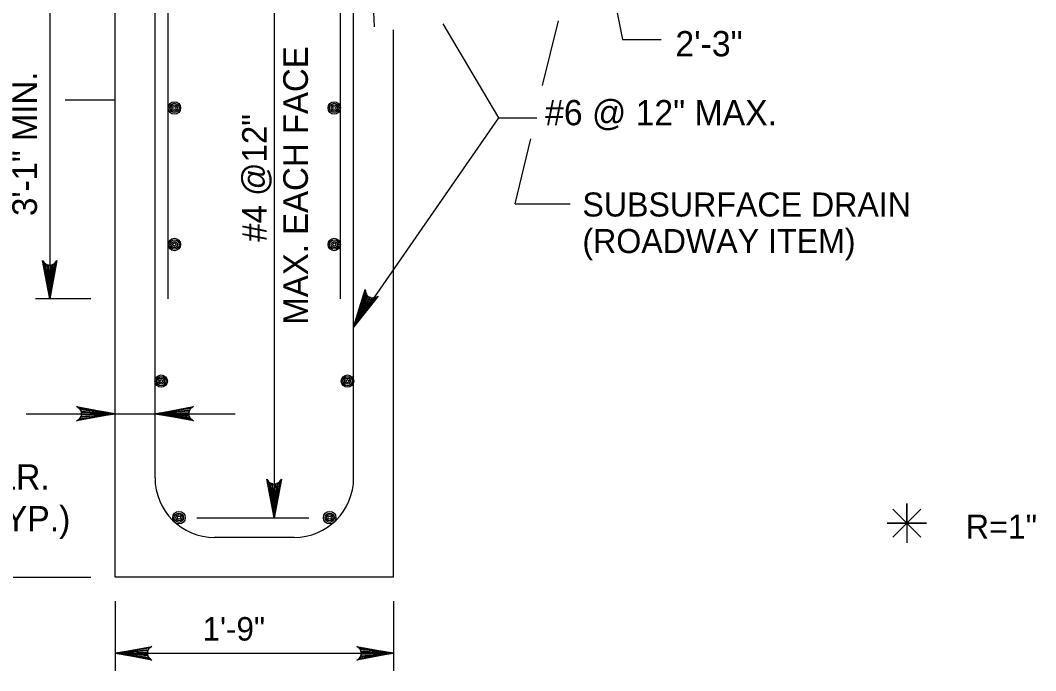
# Model space of a CAD drawing. Extents: x 638167 to 640248, y 296544 to 298920.
# Drawn here: x 639551.3 to 639681.1, y 298638.7 to 298721.8 of the extents above; entities that cross this region are included whole.
import ezdxf

# ---------------------------------------------------------------- set-up
doc = ezdxf.new("R2010")
doc.units = 0
doc.layers.add('1', color=7, linetype='Continuous')
doc.layers.add('50', color=7, linetype='Continuous')

# ---------------------------------------------------------------- blocks, each defined once
blk = doc.blocks.new('BAR')
at = {"layer": '50'}
for radius in [2, 1.5, 1, 0.5]:
    blk.add_circle((0, 0), radius, dxfattribs=at)

msp = doc.modelspace()

# ---------------------------------------------------------------- linework, layer by layer
at = {"layer": '1'}
for p, q in [((639583.8, 298762.96), (639583.8, 298658.27)), ((639563.48, 298650.66), (639563.48, 298751.04)), ((639595.38, 298750.89), (639596.57, 298721)), ((639555.1, 298737.02), (639555.1, 298686.22)), ((639568.56, 298663.36), (639568.56, 298737.02)), ((639570.25, 298686.22), (639570.25, 298737.02)), ((639592.26, 298686.22), (639592.26, 298737.02)), ((639593.95, 298663.36), (639593.95, 298737.02)), ((639627.44, 298723.85), (639628.33, 298719.38)), ((639618.11, 298713.47), (639620.12, 298721.75)), ((639599.03, 298650.66), (639599.03, 298720.59)), ((639605.33, 298721.38), (639612.48, 298709.34)), ((639628.33, 298719.38), (639633.26, 298719.38)), ((639563.48, 298711.62), (639557.09, 298711.62)), ((639612.48, 298709.34), (639593.95, 298682.63)), ((639612.48, 298709.34), (639617.35, 298709.34)), ((639614.59, 298698.39), (639616.59, 298706.68)), ((639614.59, 298698.39), (639621.63, 298698.39)), ((639560.34, 298686.22), (639553.3, 298686.22)), ((639552.1, 298671.55), (639578.82, 298671.55)), ((639573.91, 298658.27), (639588.23, 298658.27)), ((639664.66, 298657.57), (639664.66, 298657.57)), ((639586.33, 298655.74), (639576.18, 298655.74)), ((639502.18, 298650.66), (639560.34, 298650.66)), ((639599.03, 298650.66), (639563.48, 298650.66)), ((639563.48, 298647.62), (639563.48, 298638.72)), ((639599.03, 298647.62), (639599.03, 298638.72)), ((639563.48, 298640.95), (639599.03, 298640.95))]:
    msp.add_line(p, q, dxfattribs=at)
for points in [[(639555.1, 298686.22), (639554.18, 298691.15), (639554.31, 298690.96), (639554.44, 298690.77), (639554.61, 298690.67), (639554.77, 298690.58), (639554.94, 298690.55), (639555.1, 298690.52), (639555.27, 298690.55), (639555.43, 298690.58), (639555.6, 298690.67), (639555.76, 298690.77), (639555.89, 298690.96), (639556.03, 298691.15), (639555.1, 298686.22), (639555.89, 298690.96), (639555.76, 298690.77), (639555.1, 298686.22), (639555.6, 298690.67), (639555.43, 298690.58), (639555.1, 298686.22), (639555.27, 298690.55), (639555.1, 298690.52), (639555.1, 298686.22), (639554.94, 298690.55), (639554.77, 298690.58), (639555.1, 298686.22), (639554.61, 298690.67), (639554.44, 298690.77), (639555.1, 298686.22), (639554.31, 298690.96)], [(639593.95, 298682.63), (639595.43, 298687.43), (639595.46, 298687.2), (639595.49, 298686.97), (639595.59, 298686.81), (639595.69, 298686.64), (639595.82, 298686.54), (639595.96, 298686.44), (639596.12, 298686.39), (639596.27, 298686.33), (639596.47, 298686.34), (639596.66, 298686.35), (639596.86, 298686.46), (639597.07, 298686.57), (639593.95, 298682.63), (639596.86, 298686.46), (639596.66, 298686.35), (639593.95, 298682.63), (639596.47, 298686.34), (639596.27, 298686.33), (639593.95, 298682.63), (639596.12, 298686.39), (639595.96, 298686.44), (639593.95, 298682.63), (639595.82, 298686.54), (639595.69, 298686.64), (639593.95, 298682.63), (639595.59, 298686.81), (639595.49, 298686.97), (639593.95, 298682.63), (639595.46, 298687.2)], [(639563.48, 298671.55), (639558.54, 298670.63), (639558.73, 298670.76), (639558.92, 298670.89), (639559.02, 298671.06), (639559.12, 298671.22), (639559.15, 298671.39), (639559.18, 298671.55), (639559.15, 298671.72), (639559.12, 298671.88), (639559.02, 298672.05), (639558.92, 298672.21), (639558.73, 298672.35), (639558.54, 298672.48), (639563.48, 298671.55), (639558.73, 298672.35), (639558.92, 298672.21), (639563.48, 298671.55), (639559.02, 298672.05), (639559.12, 298671.88), (639563.48, 298671.55), (639559.15, 298671.72), (639559.18, 298671.55), (639563.48, 298671.55), (639559.15, 298671.39), (639559.12, 298671.22), (639563.48, 298671.55), (639559.02, 298671.06), (639558.92, 298670.89), (639563.48, 298671.55), (639558.73, 298670.76)], [(639568.56, 298671.55), (639573.49, 298672.48), (639573.3, 298672.35), (639573.11, 298672.21), (639573.01, 298672.05), (639572.91, 298671.88), (639572.88, 298671.72), (639572.86, 298671.55), (639572.88, 298671.39), (639572.91, 298671.22), (639573.01, 298671.06), (639573.11, 298670.89), (639573.3, 298670.76), (639573.49, 298670.63), (639568.56, 298671.55), (639573.3, 298670.76), (639573.11, 298670.89), (639568.56, 298671.55), (639573.01, 298671.06), (639572.91, 298671.22), (639568.56, 298671.55), (639572.88, 298671.39), (639572.86, 298671.55), (639568.56, 298671.55), (639572.88, 298671.72), (639572.91, 298671.88), (639568.56, 298671.55), (639573.01, 298672.05), (639573.11, 298672.21), (639568.56, 298671.55), (639573.3, 298672.35)], [(639583.8, 298658.27), (639582.87, 298663.2), (639583, 298663.01), (639583.13, 298662.82), (639583.3, 298662.73), (639583.47, 298662.63), (639583.63, 298662.6), (639583.8, 298662.57), (639583.96, 298662.6), (639584.13, 298662.63), (639584.29, 298662.73), (639584.46, 298662.82), (639584.59, 298663.01), (639584.72, 298663.2), (639583.8, 298658.27), (639584.59, 298663.01), (639584.46, 298662.82), (639583.8, 298658.27), (639584.29, 298662.73), (639584.13, 298662.63), (639583.8, 298658.27), (639583.96, 298662.6), (639583.8, 298662.57), (639583.8, 298658.27), (639583.63, 298662.6), (639583.47, 298662.63), (639583.8, 298658.27), (639583.3, 298662.73), (639583.13, 298662.82), (639583.8, 298658.27), (639583, 298663.01)], [(639662.88, 298659.35), (639666.44, 298655.78), (639664.66, 298657.57), (639666.44, 298659.35), (639662.88, 298655.78), (639664.66, 298657.57), (639662.14, 298657.57), (639667.18, 298657.57), (639664.66, 298657.57), (639664.66, 298660.09), (639664.66, 298655.05)], [(639563.48, 298640.95), (639568.17, 298641.83), (639567.99, 298641.7), (639567.81, 298641.58), (639567.72, 298641.42), (639567.63, 298641.26), (639567.6, 298641.1), (639567.57, 298640.95), (639567.6, 298640.79), (639567.63, 298640.63), (639567.72, 298640.47), (639567.81, 298640.32), (639567.99, 298640.19), (639568.17, 298640.07), (639563.48, 298640.95), (639567.99, 298640.19), (639567.81, 298640.32), (639563.48, 298640.95), (639567.72, 298640.47), (639567.63, 298640.63), (639563.48, 298640.95), (639567.6, 298640.79), (639567.57, 298640.95), (639563.48, 298640.95), (639567.6, 298641.1), (639567.63, 298641.26), (639563.48, 298640.95), (639567.72, 298641.42), (639567.81, 298641.58), (639563.48, 298640.95), (639567.99, 298641.7)], [(639599.03, 298640.95), (639594.34, 298640.07), (639594.52, 298640.19), (639594.7, 298640.32), (639594.79, 298640.47), (639594.88, 298640.63), (639594.91, 298640.79), (639594.94, 298640.95), (639594.91, 298641.1), (639594.88, 298641.26), (639594.79, 298641.42), (639594.7, 298641.58), (639594.52, 298641.7), (639594.34, 298641.83), (639599.03, 298640.95), (639594.52, 298641.7), (639594.7, 298641.58), (639599.03, 298640.95), (639594.79, 298641.42), (639594.88, 298641.26), (639599.03, 298640.95), (639594.91, 298641.1), (639594.94, 298640.95), (639599.03, 298640.95), (639594.91, 298640.79), (639594.88, 298640.63), (639599.03, 298640.95), (639594.79, 298640.47), (639594.7, 298640.32), (639599.03, 298640.95), (639594.52, 298640.19)]]:
    msp.add_lwpolyline(points, dxfattribs=at)
for centre, start, end in [((639576.18, 298663.36), 180, 270), ((639586.33, 298663.36), 270, 0)]:
    msp.add_arc(centre, 7.62, start, end, dxfattribs=at)

# ---------------------------------------------------------------- block references
at = {"layer": '1', "xscale": 0.3968757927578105, "yscale": 0.39687579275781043, "rotation": -90.00000000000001}
for p in [(639571.04, 298710.62), (639591.47, 298710.62), (639571.04, 298693.17), (639591.47, 298693.17), (639569.35, 298675.72), (639593.16, 298675.72), (639571.62, 298658.27), (639590.89, 298658.27)]:
    msp.add_blockref('BAR', p, dxfattribs=at)

# ---------------------------------------------------------------- texts
at = {"layer": '1'}
for s, height, p in [('2\'-3"', 3.226, (639635.08, 298717.22)), ('#6 @ 12" MAX.', 3.2256, (639618.42, 298708.41)), ('CLR.', 3.226, (639545.28, 298661.86)), ('(TYP.)', 3.226, (639545.28, 298656.53)), ('R=1"', 3.072, (639672.2, 298655.59)), ('1\'-9"', 3, (639574.64, 298642.57))]:
    msp.add_text(s, height=height, dxfattribs=at).set_placement(p)
for s, height, rotation, p in [('MAX. EACH FACE', 3.15, 90, (639588.1, 298682.93)), ('3\'-1" MIN.', 3.15, 90, (639553.47, 298696.82)), ('#4 @12"', 3.15, 90, (639582.85, 298693.53)), ('SUBSURFACE DRAIN', 3.072, 360, (639623.19, 298696.75)), ('(ROADWAY ITEM)', 3.072, 360, (639623.19, 298692.08))]:
    msp.add_text(s, height=height, rotation=rotation, dxfattribs=at).set_placement(p)

doc.saveas('drawing.dxf')
